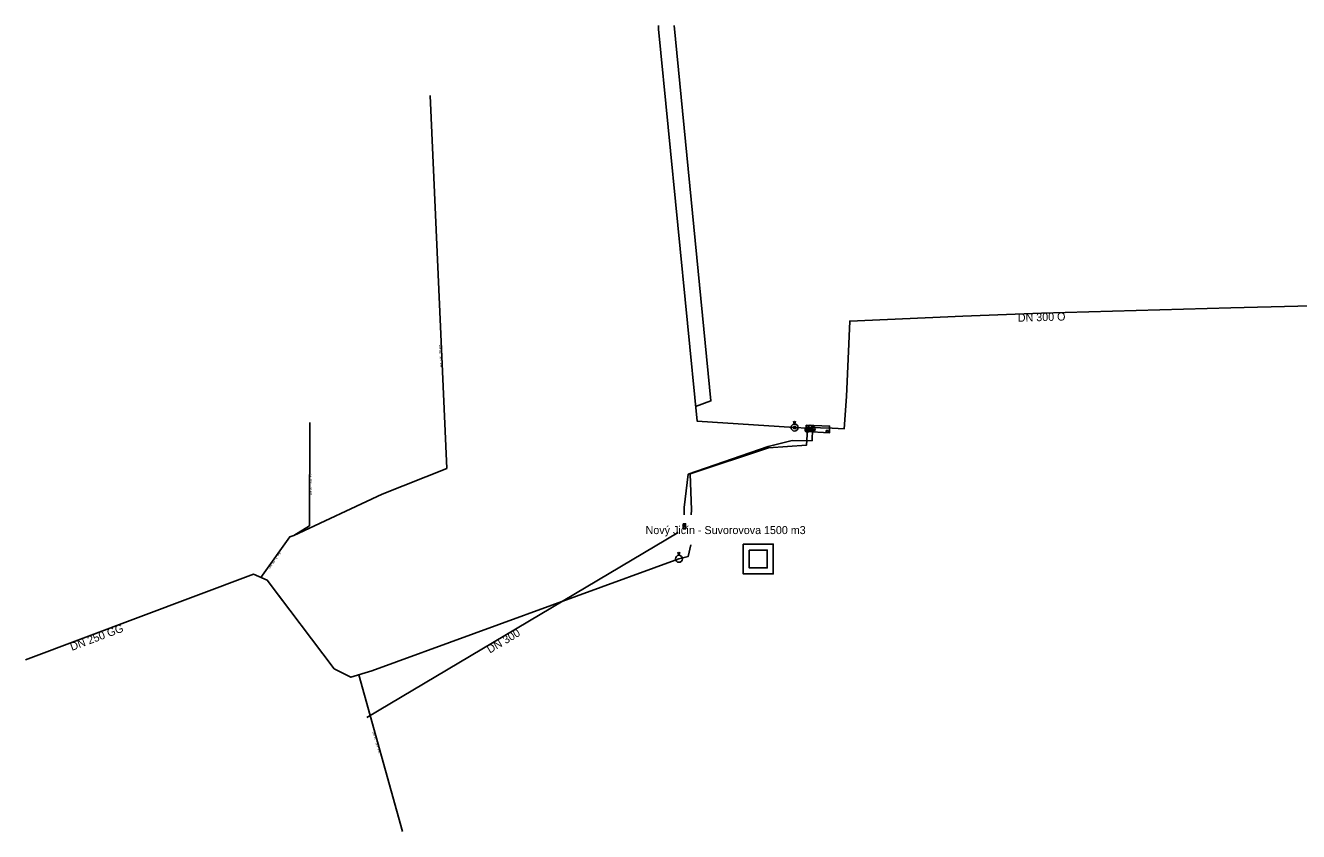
# Model space of a CAD drawing. Extents: x -491015 to -489994, y -1125687 to -1125176.
# Drawn here: x -491015 to -490759.8, y -1125338.2 to -1125176.5 of the extents above; entities that cross this region are included whole.
import ezdxf

# ---------------------------------------------------------------- set-up
doc = ezdxf.new("R2010")
doc.units = 0
for name, color, linetype in [('_odpadni_voda_', 7, 'Continuous'), ('_podz_obvod_sachty_', 7, 'Continuous'), ('_pripojka_prevzato_z_dokumentace_', 7, 'Continuous'), ('_pripojka_priblizne_', 7, 'Continuous'), ('_voda_projekt_smvak_', 7, 'Continuous'), ('_voda_smvak_prevzato_z_dokumentace_', 7, 'Continuous'), ('Default', 7, 'Continuous'), ('MoLevel 21', 7, 'Continuous'), ('MoLevel 22', 7, 'Continuous'), ('MoLevel 27', 7, 'Continuous'), ('MoLevel 30', 7, 'Continuous'), ('MoLevel 32', 7, 'Continuous'), ('MoLevel 35', 7, 'Continuous'), ('MoLevel 39', 7, 'Continuous'), ('MoLevel 42', 7, 'Continuous'), ('MoLevel 46', 7, 'Continuous'), ('MoLevel 55', 7, 'Continuous')]:
    doc.layers.add(name, color=color, linetype=linetype)

# ---------------------------------------------------------------- blocks, each defined once
blk = doc.blocks.new('_vodojem_')
at = {"layer": 'Default'}
blk.add_lwpolyline([(-0.05, 0.05), (0.05, 0.05), (0.05, -0.05), (-0.05, -0.05), (-0.05, 0.05)], dxfattribs=at)
blk.add_lwpolyline([(-0.03, 0.03), (0.03, 0.03), (0.03, -0.03), (-0.03, -0.03)], close=True, dxfattribs=at)
blk = doc.blocks.new('_uzaver_')
at = {"layer": 'Default'}
for p, q in [((-0.035, -0.035), (0.035, 0.035)), ((0.035, -0.035), (-0.035, 0.035))]:
    blk.add_line(p, q, dxfattribs=at)
for radius in [0.05, 0.0025]:
    blk.add_circle((0, 0), radius, dxfattribs=at)
blk = doc.blocks.new('_redukcni_ventil_')
at = {"layer": 'Default'}
blk.add_lwpolyline([(-0.05, -0.025), (0.05, -0.025), (0.05, 0.025), (-0.05, 0.025), (-0.05, -0.025)], dxfattribs=at)
blk.add_lwpolyline([(-0.05, 0), (0.05, -0.025), (0.05, 0.025)], close=True, dxfattribs=at)
blk = doc.blocks.new('_sachta_voda_')
at = {"layer": 'Default'}
blk.add_lwpolyline([(-0.01, 0.065), (0, 0.035), (0.01, 0.065)], dxfattribs=at)
blk.add_circle((0, 0), 0.035, dxfattribs=at)
blk = doc.blocks.new('_poklop_voda_')
at = {"layer": 'Default'}
blk.add_lwpolyline([(-0.02, 0.02), (0.02, 0.02), (0.02, -0.02), (-0.02, -0.02), (-0.02, 0.02)], dxfattribs=at)

msp = doc.modelspace()

# ---------------------------------------------------------------- linework, layer by layer
at = {"layer": '_odpadni_voda_'}
msp.add_line((-490884.14, -1125278.2), (-490946.57, -1125315.32), dxfattribs=at)
at = {"layer": '_podz_obvod_sachty_'}
msp.add_lwpolyline([(-490858.5, -1125256.71), (-490853.77, -1125256.86), (-490853.81, -1125258.24), (-490858.52, -1125257.97)], close=True, dxfattribs=at)
at = {"layer": '_pripojka_prevzato_z_dokumentace_'}
msp.add_line((-490966.53, -1125287.79), (-490963.44, -1125291.86), dxfattribs=at)
for points in [[(-490961.21, -1125278.79), (-490943.48, -1125270.51), (-490930.53, -1125265.36), (-490933.83, -1125190.57)], [(-490961.21, -1125278.79), (-490958.08, -1125276.86), (-490958, -1125256.17)], [(-490967.79, -1125287.25), (-490962.01, -1125279.09), (-490961.21, -1125278.79)]]:
    msp.add_lwpolyline(points, dxfattribs=at)
at = {"layer": '_pripojka_priblizne_'}
msp.add_line((-490939.42, -1125338.21), (-490948.13, -1125306.77), dxfattribs=at)
at = {"layer": '_voda_projekt_smvak_'}
msp.add_lwpolyline([(-490884.94, -1125176.48), (-490877.56, -1125251.81), (-490880.63, -1125252.96)], dxfattribs=at)
at = {"layer": '_voda_smvak_prevzato_z_dokumentace_'}
for p, q in [((-490858.18, -1125257.25), (-490858.2, -1125257.58)), ((-490858.18, -1125257.25), (-490857.68, -1125257.21)), ((-490857.68, -1125257.21), (-490857.17, -1125257.17)), ((-490857.17, -1125257.17), (-490857.18, -1125257.43)), ((-490855.63, -1125257.21), (-490857.17, -1125257.17))]:
    msp.add_line(p, q, dxfattribs=at)
for points in [[(-490888.11, -1125176.48), (-490888.09, -1125177.25), (-490880.34, -1125255.86), (-490860.8, -1125257.15), (-490858.18, -1125257.25)], [(-490748.71, -1125268.96), (-490749.97, -1125268.7), (-490750.21, -1125262.93), (-490749.47, -1125247.72), (-490749.16, -1125232.51), (-490773.35, -1125233.17), (-490811.27, -1125234.19), (-490827.06, -1125234.84), (-490849.74, -1125235.78), (-490850.39, -1125250.92), (-490850.82, -1125257.39), (-490853.25, -1125257.28), (-490855.63, -1125257.21)], [(-490857.18, -1125257.43), (-490857.28, -1125259.79), (-490861.27, -1125259.77), (-490866.06, -1125260.99), (-490882.11, -1125266.52), (-490882.95, -1125273.17), (-490882.9, -1125274.69)], [(-490858.2, -1125257.58), (-490858.4, -1125260.66), (-490866.01, -1125261.21), (-490881.72, -1125266.43), (-490881.44, -1125273.69), (-490881.51, -1125274.7)], [(-491015, -1125303.74), (-490969.25, -1125286.6), (-490966.53, -1125287.79), (-490953.07, -1125305.54), (-490949.74, -1125307.25), (-490945.54, -1125305.98), (-490883.98, -1125283.49), (-490882.13, -1125283.05), (-490881.58, -1125280.71)]]:
    msp.add_lwpolyline(points, dxfattribs=at)

# ---------------------------------------------------------------- block references
at = {"layer": 'MoLevel 21', "xscale": 60, "yscale": 60}
msp.add_blockref('_vodojem_', (-490868.07, -1125283.53), dxfattribs=at)
at = {"layer": 'MoLevel 27', "xscale": 10, "yscale": 10}
for p in [(-490858.2, -1125257.58), (-490857.68, -1125257.21), (-490857.18, -1125257.43)]:
    msp.add_blockref('_uzaver_', p, dxfattribs=at)
at = {"layer": 'MoLevel 30', "xscale": 20, "yscale": 20}
for p in [(-490860.8, -1125257.15), (-490883.98, -1125283.49)]:
    msp.add_blockref('_sachta_voda_', p, dxfattribs=at)
at = {"layer": 'MoLevel 39', "xscale": 10, "yscale": 9.999999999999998, "rotation": -89.9417985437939}
msp.add_blockref('_redukcni_ventil_', (-490882.88, -1125276.95), dxfattribs=at)
at = {"layer": 'MoLevel 42', "xscale": 10, "yscale": 10}
for p in [(-490860.8, -1125257.15), (-490857.95, -1125257.75), (-490854.28, -1125257.95)]:
    msp.add_blockref('_poklop_voda_', p, dxfattribs=at)

# ---------------------------------------------------------------- texts
at = {"layer": 'MoLevel 22'}
msp.add_text('Nový Jičín - Suvorovova 1500 m3', height=1.6049, dxfattribs=at).set_placement((-490890.66, -1125278.53))
at = {"layer": 'MoLevel 32'}
msp.add_text("DN 20 - 3/4'' PE", height=0.455, rotation=285.4861, dxfattribs=at).set_placement((-490945.43, -1125318.22))
at = {"layer": 'MoLevel 35'}
msp.add_text('DN 300', height=1.605, rotation=30.7362, dxfattribs=at).set_placement((-490921.89, -1125302.52))
at = {"layer": 'MoLevel 46'}
for s, rotation, p in [('DN 300 O', 1.5496, (-490816.01, -1125235.93)), ('DN 250 GG', 20.5466, (-491005.68, -1125301.97))]:
    msp.add_text(s, height=1.605, rotation=rotation, dxfattribs=at).set_placement(p)
at = {"layer": 'MoLevel 55'}
for s, rotation, p in [("DN 32 - 5/4'' PE", 272.5272, (-490932.08, -1125240.56)), ("DN 32 - 5/4'' PE", 89.7681, (-490957.6, -1125270.73)), ("DN 50 - 2'' PE", 54.6987, (-490965.99, -1125285.5))]:
    msp.add_text(s, height=0.455, rotation=rotation, dxfattribs=at).set_placement(p)

doc.saveas('drawing.dxf')
